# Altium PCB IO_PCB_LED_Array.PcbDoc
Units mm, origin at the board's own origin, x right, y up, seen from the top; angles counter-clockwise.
Board outline 90.28 x 70.62 mm, 2 copper layers (Top Layer, Bottom Layer), stack 1.57 mm thick; 4 components, 0 nets, 8 pads, 0 vias.
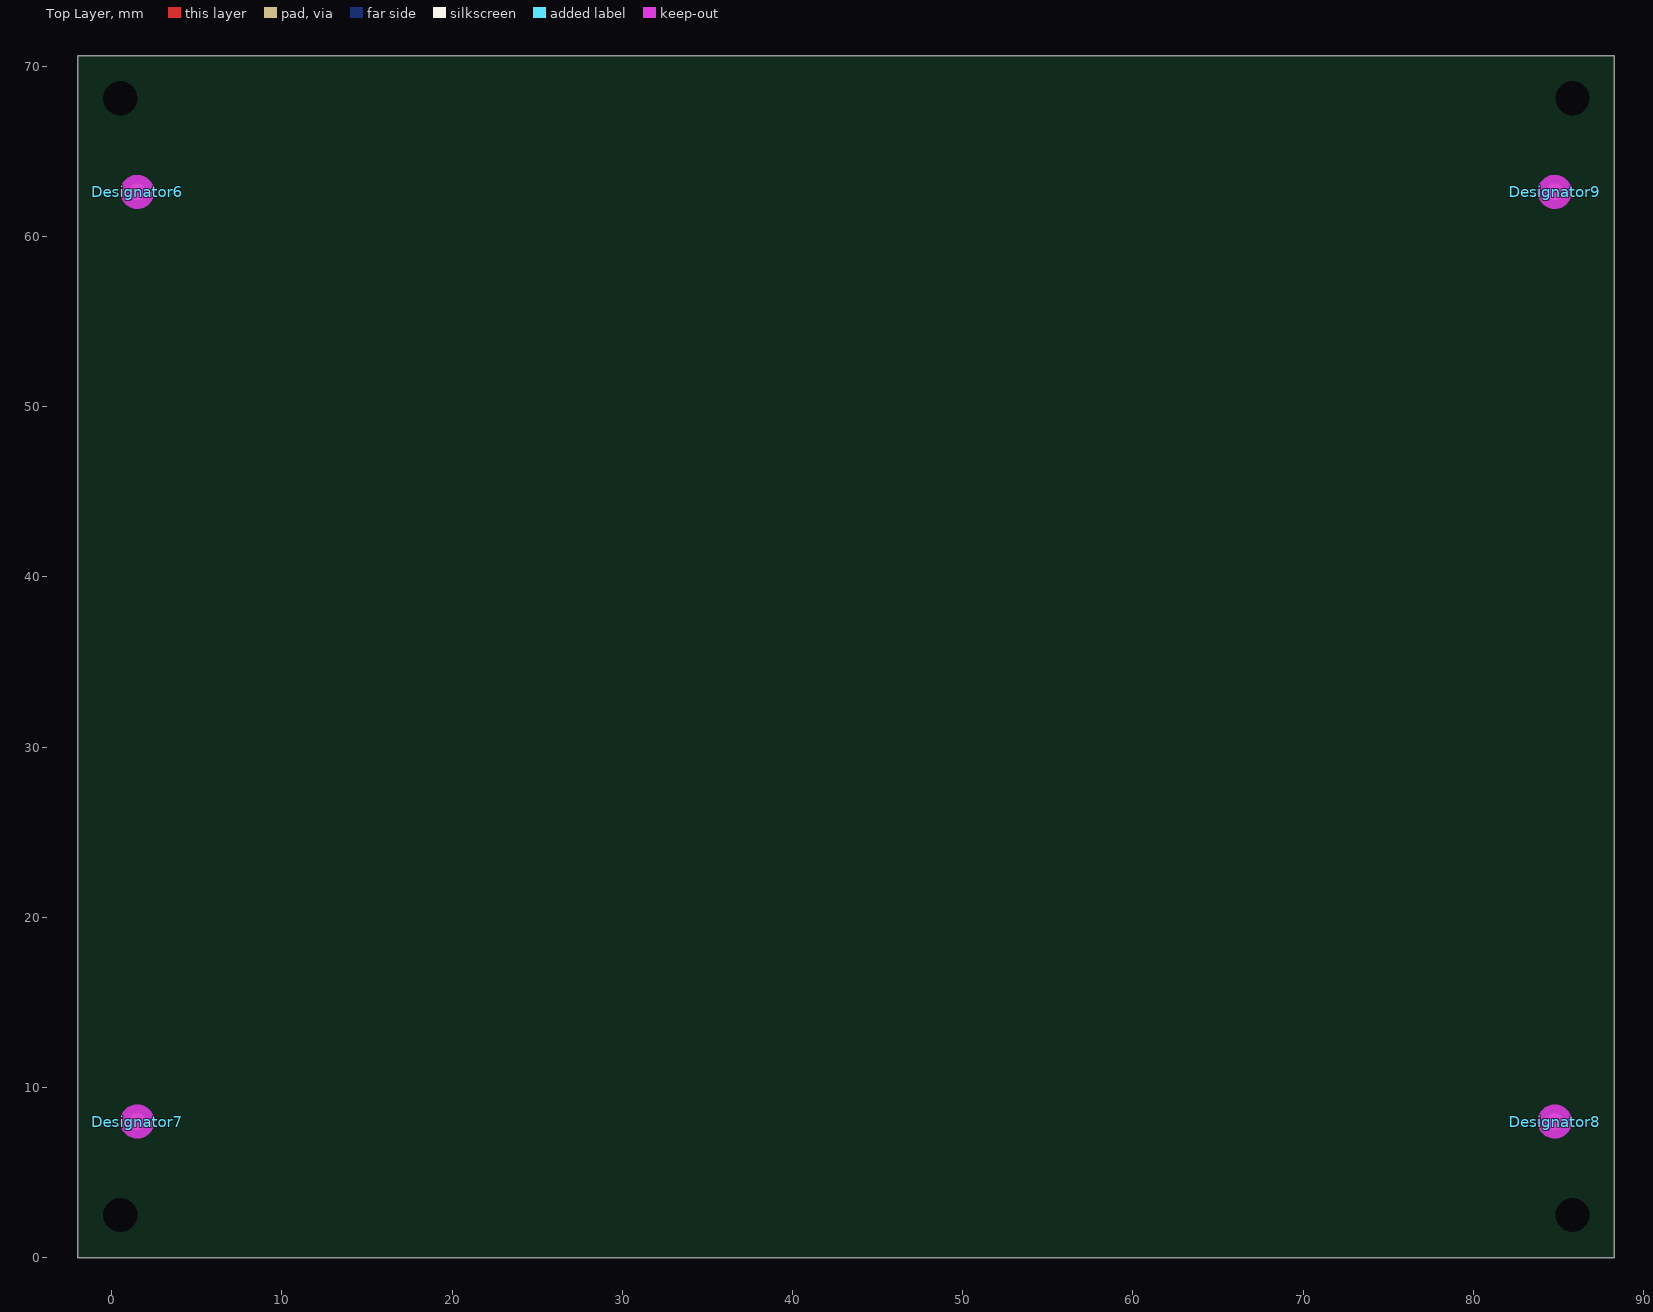
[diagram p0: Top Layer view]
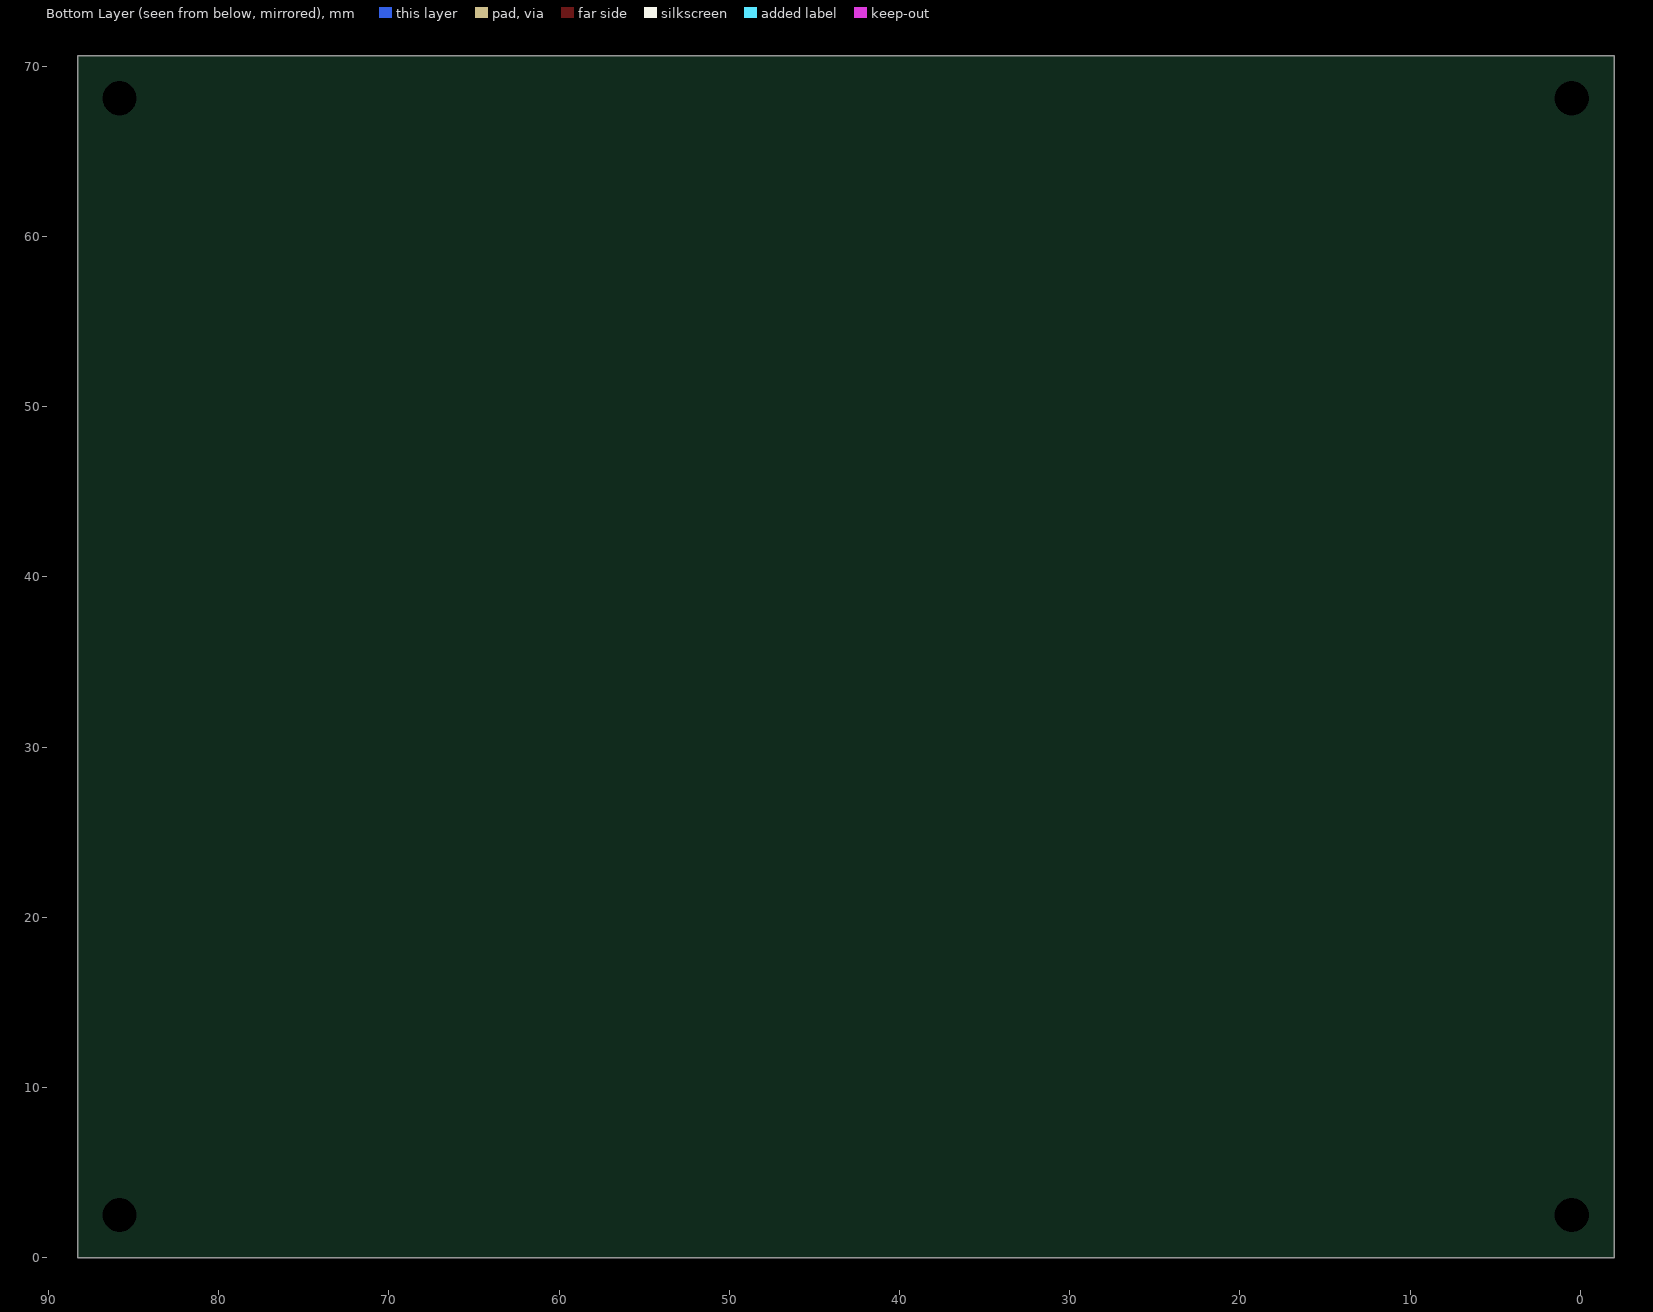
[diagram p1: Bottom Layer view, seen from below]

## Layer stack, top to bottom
Top Solder: solder mask 0.01, Solder Resist, Dk 3.5
Top Layer: signal copper 0.035
Dielectric 1: dielectric 1.5, FR-4, Dk 4.8
Bottom Layer: signal copper 0.035
Bottom Solder: solder mask 0.01, Solder Resist, Dk 3.5

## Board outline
-2,0 -2,70.62 88.28,70.62 88.28,0

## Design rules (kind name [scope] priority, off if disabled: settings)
Clearance [All] p1: gap=0.254 ignorepadtopadclearanceinfootprint=FALSE
PolygonConnect [All] p1: connectstyle=Relief reliefconductorwidth=0.254 reliefentries=4 polygonreliefangle="90 Angle" airgapwidth=0.254
RoutingVias [All] p1: holewidth=0.711 width=1.27 viastyle="Through Hole" minholewidth=0.711 minwidth=1.27 maxholewidth=0.711 maxwidth=1.27
SolderMaskExpansion [All] p1: expansion=0.102 istentingtop=FALSE
Width [All] p1: maxlimit=0.254 minlimit=0.254 preferedwidth=0.254
30 further rules are at their usual default settings.

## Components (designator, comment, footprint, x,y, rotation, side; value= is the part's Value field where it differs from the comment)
Designator6 "Comment" FID1X2R 1.5,62.62 r0 top
Designator7 "Comment" FID1X2R 1.5,8 r0 top
Designator8 "Comment" FID1X2R 84.78,8 r0 top
Designator9 "Comment" FID1X2R 84.78,62.62 r0 top

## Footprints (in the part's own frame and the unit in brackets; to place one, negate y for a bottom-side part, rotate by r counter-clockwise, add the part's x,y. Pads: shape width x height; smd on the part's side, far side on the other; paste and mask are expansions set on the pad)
FID1X2R [mm] "Fiducial - Round 1x2mm"
  round 1 smd mask-2539.97: 1(0,0)
  Top Layer keep-out circle w1: c0,0 r0.5

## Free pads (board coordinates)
  round 0 hole 2 unplated: 29(0.5,2.5) 29(0.5,68.12) 29(85.836,2.5) 29(85.836,68.12)

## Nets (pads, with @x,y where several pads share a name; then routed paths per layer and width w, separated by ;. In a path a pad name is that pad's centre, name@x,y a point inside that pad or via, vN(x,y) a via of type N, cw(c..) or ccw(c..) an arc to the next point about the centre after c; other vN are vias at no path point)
pads on no net: Designator6.1 Designator7.1 Designator8.1 Designator9.1

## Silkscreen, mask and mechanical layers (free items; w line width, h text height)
Mechanical 1:
  the board outline again, w0.254
V Cut:
  lines w1.02: -3,23.37 89.28,23.37 ; -3,47.25 89.28,47.25 ; 3.51,-3 3.51,73.62 ; 29.93,-2.873 29.93,73.747 ; 56.35,-3 56.35,73.62 ; 82.77,-3 82.77,73.62
  text "V-CUT" at 30.738,74.93 h1.52 r90
  text "V-CUT" at 4.318,74.803 h1.52 r90
  text "V-CUT" at 57.158,74.803 h1.52 r90
  text "V-CUT" at 83.578,74.803 h1.52 r90
  text "V-CUT" at 90.424,46.478 h1.52
  text "V-CUT" at 90.424,22.598 h1.52

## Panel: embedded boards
"IO_PCB_LED.PcbDoc" at 4.02,0, 3 rows x 3 columns, spacing 23.88 x 26.42, rotation 0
